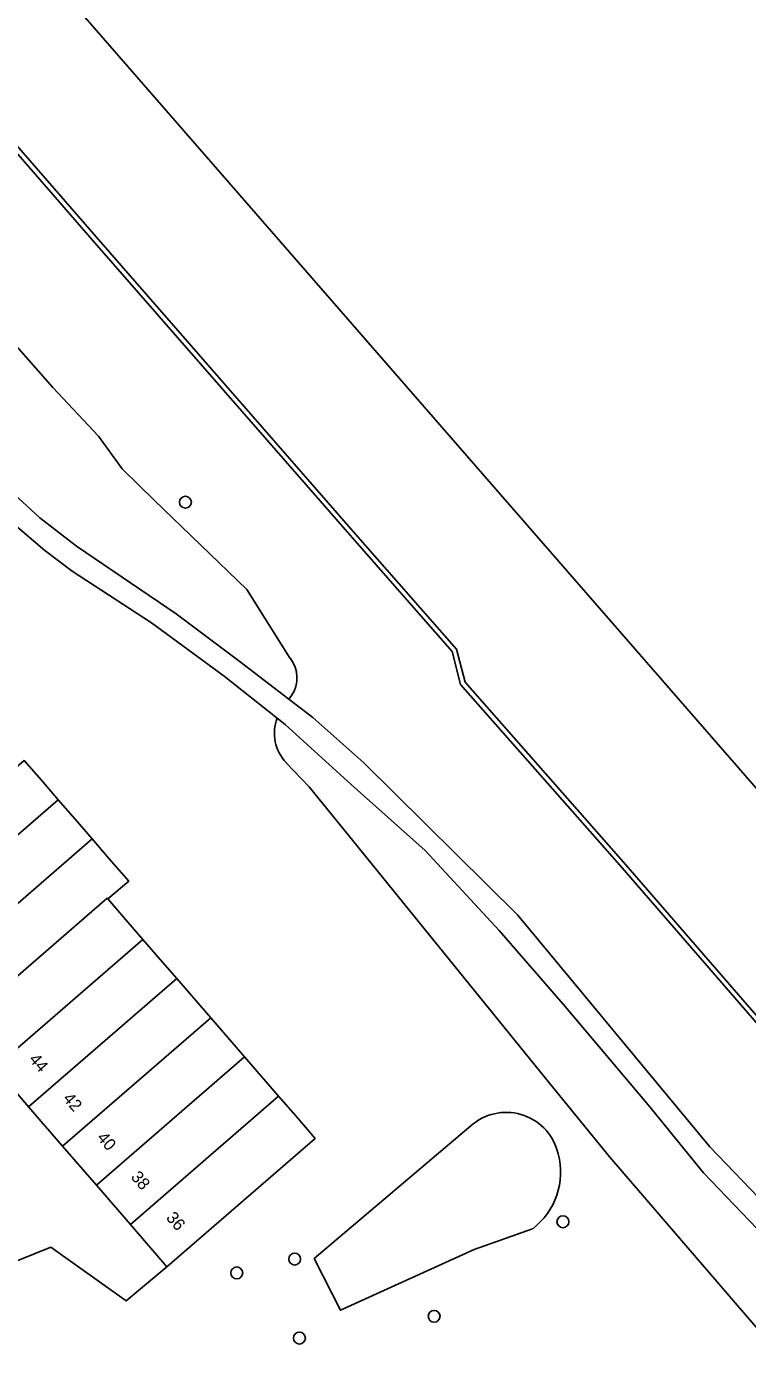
# Model space of a CAD drawing. Extents: x 156661 to 157576, y 383570 to 384425.
# Drawn here: x 156956.8 to 157016.4, y 384208.3 to 384317.7 of the extents above; entities that cross this region are included whole.
import ezdxf

# ---------------------------------------------------------------- set-up
doc = ezdxf.new("R2010")
doc.units = 0
for name, color, linetype in [('IMGEO_Boom', 7, 'Continuous'), ('IMGEO_Groenvoorziening', 7, 'Continuous'), ('IMGEO_Houtwal', 7, 'Continuous'), ('IMGEO_Kademuur', 7, 'Continuous'), ('IMGEO_Loofbos', 7, 'Continuous'), ('IMGEO_Meer_plas_ven_vijver', 7, 'Continuous'), ('IMGEO_Muur', 7, 'Continuous'), ('IMGEO_Pand', 7, 'Continuous'), ('IMGEO_Pand_nummerreeks', 7, 'Continuous'), ('IMGEO_Voetpad_halfverhard', 7, 'Continuous'), ('IMGEO_Waterloop', 7, 'Continuous')]:
    doc.layers.add(name, color=color, linetype=linetype)

msp = doc.modelspace()

# ---------------------------------------------------------------- linework, layer by layer
at = {"layer": 'IMGEO_Boom'}
for centre in [(156969.96, 384278.46), (157001.12, 384219.07), (156978.98, 384215.99), (156974.2, 384214.85), (156990.49, 384211.27), (156979.37, 384209.47)]:
    msp.add_circle(centre, 0.489, dxfattribs=at)
at = {"layer": 'IMGEO_Groenvoorziening'}
for points in [[(156977.53, 384260.64), (156973.15, 384264.09), (156967.17, 384268.51), (156960.61, 384272.78), (156958.35, 384274.47), (156955.36, 384277.02)], [(156956.66, 384257.13), (156958.07, 384255.51), (156959.46, 384253.9), (156960.85, 384252.3), (156962.27, 384250.67), (156963.68, 384249.03), (156965.28, 384247.19), (156963.57, 384245.71), (156965.05, 384243.99), (156966.45, 384242.38), (156967.88, 384240.72), (156969.25, 384239.14), (156970.65, 384237.53), (156972.05, 384235.9), (156973.46, 384234.28), (156974.85, 384232.67), (156976.24, 384231.07), (156977.65, 384229.43), (156979.07, 384227.8), (156980.67, 384225.95), (156968.44, 384215.36), (156965.08, 384212.54), (156958.84, 384216.97), (156951.07, 384213.83)], [(157004.98, 384224.39), (157000, 384230.52), (156984.21, 384250), (156980.17, 384254.98), (156978.29, 384256.96)], [(156980.6, 384216.03), (156993.72, 384227.16)], [(157041.54, 384183.09), (157019.08, 384208.03), (157004.98, 384224.39)], [(156998.62, 384218.5), (156993.8, 384216.77), (156982.75, 384211.77), (156980.6, 384216.03)]]:
    msp.add_lwpolyline(points, dxfattribs=at)
for centre, radius, start, end in [((156980.78, 384259.39), 3.48, 158.9292, 224.3425), ((156996.44, 384223.71), 4.39, 12.6468, 128.2021), ((156995.06, 384223.16), 5.87, 307.3918, 14.9384)]:
    msp.add_arc(centre, radius, start, end, dxfattribs=at)
at = {"layer": 'IMGEO_Houtwal'}
for points in [[(157023.54, 384228.05), (157006.01, 384248.27), (156992.67, 384263.41), (156991.97, 384266.15), (156983.52, 384275.77), (156962.3, 384300.1), (156938.72, 384327.24)], [(156931.89, 384319.27), (156933.49, 384317.37), (156941.08, 384308.28), (156959.02, 384287.93), (156962.79, 384283.9), (156964.73, 384281.22), (156967.39, 384278.64), (156975.02, 384271.25), (156978.62, 384265.56)], [(156978.72, 384262.51), (156978.51, 384262.21), (156980.47, 384260.7), (156984.68, 384256.94), (156997.37, 384244.41), (157013.26, 384225.25), (157023.32, 384214.78), (157026.81, 384211.27), (157030.88, 384207.6), (157037.59, 384202.58), (157040.64, 384199.44), (157043.35, 384196.04), (157046.38, 384190.23), (157047.65, 384186.15), (157047.82, 384185.09), (157048.07, 384183.16), (157051.02, 384185.6), (157062.85, 384170.34), (157068.99, 384162.42), (157107.42, 384120.01)], [(157001.14, 384237.04), (156995.85, 384243.12), (156989.76, 384249.71), (156983.63, 384255.15), (156978.19, 384260.12), (156977.53, 384260.64)], [(156978.29, 384256.96), (156980.17, 384254.98), (156984.21, 384250), (157000, 384230.52), (157004.98, 384224.39), (157019.08, 384208.03), (157041.54, 384183.09)], [(157046.32, 384181.83), (157045.67, 384185.37), (157044.28, 384189.57), (157041.77, 384194.89), (157038.88, 384198.43), (157036.64, 384200.85), (157034.17, 384202.8), (157029.91, 384205.62), (157025.53, 384209.53), (157017.8, 384217.82), (157012.72, 384223.1), (157008.16, 384228.71), (157001.14, 384237.04)]]:
    msp.add_lwpolyline(points, dxfattribs=at)
for centre, radius, start, end in [((156976.58, 384263.97), 2.59, 325.6743, 37.9266), ((156980.78, 384259.39), 3.48, 158.9292, 224.3425)]:
    msp.add_arc(centre, radius, start, end, dxfattribs=at)
at = {"layer": 'IMGEO_Kademuur'}
msp.add_lwpolyline([(157006.31, 384248.53), (156993.04, 384263.6), (156992.33, 384266.34), (156983.82, 384276.03), (156962.6, 384300.36), (156939.02, 384327.5), (156926.02, 384342.63), (156925.56, 384342.27), (156926.89, 384340.7), (156928.32, 384339.01), (156928.69, 384338.92), (156938.72, 384327.24), (156962.3, 384300.1), (156983.52, 384275.77), (156991.97, 384266.15), (156992.67, 384263.41), (157006.01, 384248.27), (157023.54, 384228.05), (157023.76, 384227.8), (157025.56, 384225.77), (157026.74, 384224.43), (157027.04, 384224.69), (157023.85, 384228.32)], close=True, dxfattribs=at)
at = {"layer": 'IMGEO_Loofbos'}
for points in [[(156978.62, 384265.56), (156975.02, 384271.25), (156967.39, 384278.64), (156964.73, 384281.22), (156962.79, 384283.9), (156959.02, 384287.93), (156941.08, 384308.28)], [(156931.33, 384305.7), (156934.4, 384301.52), (156936.83, 384297.95), (156940.71, 384293.34), (156946.59, 384287.59), (156947.74, 384286.54), (156957.95, 384277.16), (156960.97, 384274.82), (156969.21, 384269.26), (156974.49, 384265.29), (156978.51, 384262.21), (156978.72, 384262.51)]]:
    msp.add_lwpolyline(points, dxfattribs=at)
msp.add_arc((156976.58, 384263.97), 2.59, 325.6743, 37.9266, dxfattribs=at)
at = {"layer": 'IMGEO_Meer_plas_ven_vijver'}
msp.add_lwpolyline([(156993.72, 384227.16), (156980.6, 384216.03), (156982.75, 384211.77), (156993.8, 384216.77), (156998.62, 384218.5)], dxfattribs=at)
for centre, radius, start, end in [((156996.44, 384223.71), 4.39, 12.6468, 128.2021), ((156995.06, 384223.16), 5.87, 307.3918, 14.9384)]:
    msp.add_arc(centre, radius, start, end, dxfattribs=at)
at = {"layer": 'IMGEO_Muur'}
msp.add_lwpolyline([(156968.44, 384215.36), (156965.08, 384212.54), (156958.84, 384216.97), (156951.07, 384213.83), (156949.63, 384215.46)], dxfattribs=at)
at = {"layer": 'IMGEO_Pand'}
for points in [[(156959.46, 384253.9), (156958.07, 384255.51), (156956.66, 384257.13), (156944.42, 384246.52), (156947.22, 384243.29)], [(156950.03, 384240.05), (156962.27, 384250.67), (156960.85, 384252.3), (156959.46, 384253.9), (156947.22, 384243.29)], [(156950.03, 384240.05), (156952.9, 384236.73), (156952.97, 384236.65), (156963.49, 384245.79), (156963.57, 384245.71), (156965.28, 384247.19), (156963.68, 384249.03), (156962.27, 384250.67)], [(156954.23, 384231.79), (156966.45, 384242.38), (156965.05, 384243.99), (156963.57, 384245.71), (156963.49, 384245.79), (156952.97, 384236.65), (156952.9, 384236.73), (156951.21, 384235.27)], [(156954.23, 384231.79), (156957.02, 384228.55), (156969.25, 384239.14), (156967.88, 384240.72), (156966.45, 384242.38)], [(156972.05, 384235.9), (156970.65, 384237.53), (156969.25, 384239.14), (156957.02, 384228.55), (156959.82, 384225.32)], [(156962.63, 384222.08), (156974.85, 384232.67), (156973.46, 384234.28), (156972.05, 384235.9), (156959.82, 384225.32)], [(156962.63, 384222.08), (156965.43, 384218.84), (156977.65, 384229.43), (156976.24, 384231.07), (156974.85, 384232.67)], [(156977.65, 384229.43), (156965.43, 384218.84), (156968.44, 384215.36), (156980.67, 384225.95), (156979.07, 384227.8)]]:
    msp.add_lwpolyline(points, close=True, dxfattribs=at)
at = {"layer": 'IMGEO_Voetpad_halfverhard'}
for points in [[(156929.29, 384304.96), (156930.65, 384303.57), (156935.76, 384295.86), (156940.12, 384291.28), (156946.46, 384285.34), (156955.36, 384277.02), (156958.35, 384274.47), (156960.61, 384272.78), (156967.17, 384268.51), (156973.15, 384264.09), (156977.53, 384260.64), (156978.19, 384260.12), (156983.63, 384255.15), (156989.76, 384249.71), (156995.85, 384243.12), (157001.14, 384237.04), (157008.16, 384228.71), (157012.72, 384223.1), (157017.8, 384217.82)], [(157023.32, 384214.78), (157013.26, 384225.25), (156997.37, 384244.41), (156984.68, 384256.94), (156980.47, 384260.7), (156978.51, 384262.21), (156974.49, 384265.29), (156969.21, 384269.26), (156960.97, 384274.82), (156957.95, 384277.16), (156947.74, 384286.54)], [(156951.07, 384213.83), (156958.84, 384216.97), (156965.08, 384212.54), (156968.44, 384215.36), (156965.43, 384218.84), (156962.63, 384222.08), (156959.82, 384225.32), (156957.02, 384228.55), (156954.23, 384231.79)]]:
    msp.add_lwpolyline(points, dxfattribs=at)
at = {"layer": 'IMGEO_Waterloop'}
for points in [[(156868.63, 384425.31), (156864.21, 384413.56), (156867.4, 384409.88), (156880.76, 384394.54), (156899.21, 384373.46), (156918.13, 384351.86), (156923.08, 384346.1), (156922.61, 384345.65), (156921.28, 384347.25), (156920.82, 384346.94), (156920.67, 384346.67), (156926.19, 384340.17), (156926.43, 384340.35), (156926.89, 384340.7), (156925.56, 384342.27), (156926.02, 384342.63), (156939.02, 384327.5), (156962.6, 384300.36), (156983.82, 384276.03), (156992.33, 384266.34), (156993.04, 384263.6), (157006.31, 384248.53), (157023.85, 384228.32)], [(157335.95, 383888.66), (157157.55, 384093.52), (156868.63, 384425.31)]]:
    msp.add_lwpolyline(points, dxfattribs=at)

# ---------------------------------------------------------------- texts
at = {"layer": 'IMGEO_Pand_nummerreeks'}
for s, p in [('44', (156956.99, 384232.44)), ('42', (156959.79, 384229.21)), ('40', (156962.6, 384225.97)), ('38', (156965.4, 384222.73)), ('36', (156968.31, 384219.37))]:
    msp.add_text(s, height=1, rotation=310.8741, dxfattribs=at).set_placement(p)

doc.saveas('drawing.dxf')
